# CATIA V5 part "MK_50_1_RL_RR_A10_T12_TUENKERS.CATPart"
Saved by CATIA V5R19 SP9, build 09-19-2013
Part number: MK_50_1_RL_RR_A10_T12_TUENKERS
Material "MISCHDICHTE": density 4776 kg/m3, Young's modulus 2e+11 Pa, Poisson ratio 0.266
Bounding box of the stored display mesh (mm): x -173.5 to 150.266, y -118.5 to 144, z -119.161 to 119.161
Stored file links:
  G:\Konstruktion\Modelle\Catia_V5\MK_50_1_RL_RR_A10_T12_TUENKERS.CATPart
  G:\Konstruktion\Modelle\Catia_V5\Spannarme\SPANNARM_KPL_50_A40_242838_TUENKERS.CATPart
  C:\Catia\Tuenkers_B19SP9HF86_64\win_b64\reffiles\standard\MetricThickPitch.txt
  G:\Konstruktion\Modelle\Catia_V5\Spannarme\SPANNARM_KPL_50_A10_216884_TUENKERS.CATPart
  G:\Konstruktion\Modelle\Catia_V5\MK2_50_1_A40_T00_TUENKERS.CATPart
  G:\Konstruktion\Modelle\Catia_V5\V2_50_1_BR3_ZL_ZR_RL_RR_A40_T12_TUENKERS.CATPart
  HANDHEBEL_KPL_50_63_TUENKERS.CATPart
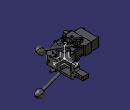
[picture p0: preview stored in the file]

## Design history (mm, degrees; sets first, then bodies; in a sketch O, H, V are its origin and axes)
AxisSystem1: origin (0, 0, 0), X (1, 0, 0), Y (0, 1, 0), Z (0, 0, 1)
Body1 (main body)
  Body2 "*DIT1\\*DIT8\\PartBody ( *SOL6 - wsp HANDHEBEL -  )"
    Solid1 "Solid.1": solid without history
  Assemble1: tool Body2
  Body3 "*DIT1\\*DIT9\\PartBody ( *SOL3 - wsp T 12 ABFRAGE -  )"
    Solid2 "Solid.1": solid without history
  Assemble2: tool Body3
  Body4 "*DIT1\\*DIT9\\Body.9 ( *SOL4 - wsp T 12 ABFRAGE -  )"
    Solid3 "Solid.1": solid without history
  Assemble3: tool Body4
  Body5 "*DIT1\\*DIT9\\Body.10 ( *SOL5 - wsp T 12 ABFRAGE -  )"
    Solid4 "Solid.1": solid without history
  Assemble4: tool Body5
  Body6 "*DIT1\\*DIT10\\*DIT17\\PartBody ( *SOL17 - wsp DREHBOLZEN -  )"
    Solid5 "Solid.1": solid without history
  Assemble5: tool Body6
  Body7 "*DIT1\\*DIT10\\*DIT18\\PartBody ( *SOL18 - wsp STOESSEL -  )"
    Solid6 "Solid.1": solid without history
  Assemble6: tool Body7
  Body8 "*DIT1\\*DIT10\\MK_MK2_50_1_A10_A11_A12_T12_081112_3D_xSET3_1.1\\PartBody ( *SOL13 - wsp GEHAEUSE -  )"
    Solid7 "Solid.1": solid without history
  Assemble7: tool Body8
  Body9 "*DIT1\\MK_MK2_50_1_A10_A11_A12_T12_081112_3D_xSET2.1\\PartBody ( *SOL1 - wsp MK_MK2 50_1 -  -Non Smart-  )"
    Solid8 "Solid.1": solid without history
  Assemble8: tool Body9
  Body10 "*DIT1\\MK_MK2_50_1_A10_A11_A12_T12_081112_3D_xSET2.1\\Body.2 ( *SOL2 - wsp MK_MK2 50_1 -  -Non Smart-  )"
    Solid9 "Solid.1": solid without history
  Assemble9: tool Body10
  Body11 "*DIT1\\MK_MK2_50_1_A10_A11_A12_T12_081112_3D_xSET2.1\\Body.3 ( *SOL24 - wsp MK_MK2 50_1 -  )"
    Solid10 "Solid.1": solid without history
  Assemble10: tool Body11
  Body12 "*DIT1\\MK_MK2_50_1_A10_A11_A12_T12_081112_3D_xSET2.1\\Body.4 ( *SOL25 - wsp MK_MK2 50_1 -  )"
    Solid11 "Solid.1": solid without history
  Assemble11: tool Body12
  Body13 "*DIT1\\MK_MK2_50_1_A10_A11_A12_T12_081112_3D_xSET2.1\\Body.5 ( *SOL26 - wsp MK_MK2 50_1 -  )"
    Solid12 "Solid.1": solid without history
  Assemble12: tool Body13
  Body14 "*DIT1\\MK_MK2_50_1_A10_A11_A12_T12_081112_3D_xSET2.1\\Body.6 ( *SOL27 - wsp MK_MK2 50_1 -  )"
    Solid13 "Solid.1": solid without history
  Assemble13: tool Body14
  Body15 "*DIT1\\MK_MK2_50_1_A10_A11_A12_T12_081112_3D_xSET2.1\\Body.7 ( *SOL28 - wsp MK_MK2 50_1 -  )"
    Solid14 "Solid.1": solid without history
  Assemble14: tool Body15
  Rotate1: Axis edge [XY plane of AxisSystem1 | ZX plane of AxisSystem1], Angle 90, ToTransfor Assemble14
Body16 "Spannarm_kpl_50_A10_216884_Tuenkers", material "Steel"
  Sketch1 on xy-plane, origin (0, 0, 0), H (1, 0, 0), V (0, 1, 0)
    line L1 (43, 144) -> (15, 144)
    line L2 (35.6421, 1.701) -> (16.9706, -16.9706)
    line L3 (9.5, 9.5) -> (9.5, -9.5)
    line L4 (9.5, 9.5) -> (-9.5, 9.5)
    line L5 (-16.9706, 16.9706) -> (-9.5, 9.5)
    line L6 (10.6421, 44.5833) -> (-16.9706, 16.9706)
    line L7 (16.5, 58.7254) -> (16.5, 78.5)
    line L8 (43, 144) -> (43, 80)
    line L9 (9.5, -9.5) -> (16.9706, -16.9706)
    point P8 (43, 9.0589)
    point P9 (16.5, 51.7188)
    reference intersected line E1 through (0, 0) direction (-1, 0)
    reference intersected line E2 through (0, 0) direction (0, 1)
    reference intersected line E3 through (0, 0) direction (-0.7071, -0.7071)
    line L10 (41.5, 78.5) -> (41.5, 15.8431)
    reference intersected line E4 through (0, 0) direction (0, 1) from yz-plane
    line L11 (15, 80) -> (15, 144)
    point P10 (15, 80)
    reference intersected line E5 through (0, 0) direction (0, 1) from yz-plane
    arc A1 centre (43, 78.5) radius 1.5 from (41.5, 78.5) to (43, 80) cw
    arc A2 centre (15, 78.5) radius 1.5 from (16.5, 78.5) to (15, 80) ccw
    arc A3 centre (21.5, 15.8431) radius 20 from (35.6421, 1.701) to (41.5, 15.8431) ccw
    arc A4 centre (-3.5, 58.7254) radius 20 from (10.6421, 44.5833) to (16.5, 58.7254) ccw
    length L3 = 19
    length L4 = 19
    angle L5 L4 = 45
    angle L3 L9 = 45
    distance L2 L6 = 48
    distance L4 L1 = 134.5
    distance P9 L4 = 42.2188
    distance L4 E1 = 9.5
    distance L3 E2 = 9.5
    distance L2 E3 = 24
    distance L10 E4 = 41.5
    distance E5 L11 = 15
    distance L7 L10 = 25
    distance L8 L11 = 28
    length L8 = 64
    radius A3 = 20
    radius A4 = 20
    radius A1 = 1.5
    radius A2 = 1.5
    length L11 = 64
    vertical: L3 V
    horizontal: L4 H
    tangency: A3 L10, L2 A3, L7 A2, L10 A1, L7 A4, L6 A4
  Pad1: profile Sketch1, direction (0, 0, 1), length 34, mirrored extent
  Chamfer1: length 0.1, angle 45, on edge [start face of Pad1 | face of Pad1 from Sketch1.L3]; edge [start face of Pad1 | face of Pad1 from Sketch1.L4]; edge [face of Pad1 from Sketch1.L4 | end face of Pad1]; edge [face of Pad1 from Sketch1.L3 | end face of Pad1]
  Sketch2 on face of Pad1 from Sketch1.L8, origin (43, 0, 0), H (0, 1, 0), V (0, 0, 1)
    line L1 (144, -10) -> (144, 10)
    line L2 (103, 10) -> (144, 10)
    arc A1 centre (103, 18) radius 8 from (103, 10) to (95, 18) cw
    line L3 (95, 18) -> (95, 21.0383)
    line L4 (-18, 34) -> (75, 34)
    line L5 (-18, 34) -> (-18, 25)
    line L6 (74, 25) -> (-18, 25)
    arc A2 centre (74, 19) radius 6 from (74, 25) to (80, 19) cw
    line L7 (80, 19) -> (80, -19)
    arc A3 centre (74, -19) radius 6 from (80, -19) to (74, -25) cw
    line L8 (-18, -25) -> (74, -25)
    line L9 (-18, -25) -> (-18, -34)
    line L10 (75, -34) -> (-18, -34)
    line L11 (95, -21.0383) -> (95, -18)
    arc A4 centre (103, -18) radius 8 from (95, -18) to (103, -10) cw
    line L12 (103, -10) -> (144, -10)
    reference intersected line E1 through (0, 0) direction (-1, 0) from xy-plane
    reference intersected line E2 through (0, 0) direction (0, 1) from zx-plane
    reference intersected line E3 through (0, 0) direction (0, 1) from zx-plane
    reference intersected line E4 through (0, 0) direction (0, 1) from zx-plane
    line L13 (-23, -39) -> (149, -39)
    line L14 (149, -39) -> (149, 39)
    line L15 (149, 39) -> (-23, 39)
    line L16 (-23, 39) -> (-23, -39)
    reference intersected line E5 through (0, 0) direction (-1, 0) from xy-plane
    reference intersected line E6 through (0, 0) direction (0, 1) from zx-plane
    line L17 (75.5176, -33.9319) -> (87.5882, -30.6976)
    point P18 (95, -24)
    arc A5 centre (85, -21.0383) radius 10 from (95, -21.0383) to (87.5882, -30.6976) cw
    arc A6 centre (75, -32) radius 2 from (75, -34) to (75.5176, -33.9319) ccw
    point P23 (75, -34)
    line L18 (87.5882, 30.6976) -> (75.5176, 33.9319)
    arc A7 centre (75, 32) radius 2 from (75, 34) to (75.5176, 33.9319) cw
    point P26 (75, 34)
    arc A8 centre (85, 21.0383) radius 10 from (87.5882, 30.6976) to (95, 21.0383) cw
    distance L12 E1 = 10
    distance L12 L2 = 20
    distance L4 L10 = 68
    distance L6 L8 = 50
    distance L10 L12 = 24
    distance L8 L10 = 9
    radius A2 = 6
    radius A3 = 6
    radius A1 = 8
    radius A4 = 8
    distance L7 E2 = 80
    distance L3 E3 = 95
    distance L1 L5 = 162
    distance E4 L1 = 144
    distance L16 L14 = 172
    distance L15 L13 = 78
    distance L13 E5 = 39
    distance L14 E6 = 149
    radius A5 = 10
    angle L10 L17 = 15
    radius A6 = 2
    distance L11 P23 = 20
    angle L4 L18 = 15
    distance P26 L3 = 20
    radius A8 = 10
    radius A7 = 2
    tangency: L6 A2, A2 L7, L7 A3, A3 L8, L3 A1, A1 L2, A4 L12, A4 L11, A5 L11, A5 L17, A6 L10, A6 L17, A7 L4, A7 L18, A8 L18, A8 L3
    vertical: L1 V, L14 V, L16 V
    horizontal: L12 H, L13 H, L15 H
    coincidence: L5 L9, L11 L3, L11 P18
  Pocket1: profile Sketch2, direction (-1, 0, 0), length 91
  Sketch3 on face of Pad1 from Sketch1.L8, origin (43, 131.0889, -0.3784), H (0, 1, 0), V (0, 0, 1)
    point P1 (3.9111, 0.3784)
    reference intersected line E1 through (0, 0.3784) direction (-1, 0) from xy-plane
    reference intersected line E2 through (-131.0889, 0) direction (0, 1) from zx-plane
    distance P1 E2 = 135
    coincidence: P1 E1
  Hole1: placed by Sketch3, at (43, 135, 0) direction (-1, 0, 0), diameter 6, through (limit type 6)
  Sketch4 on face of Pad1 from Sketch1.L8, origin (43, 113.9529, 0.5693), H (0, 1, 0), V (0, 0, 1)
    point P1 (-8.9529, -0.5693)
    reference projected point E1 (21.0471, -0.5693) from axis of face of Hole1
    reference intersected line E2 through (0, -0.5693) direction (-1, 0) from xy-plane
    distance P1 E1 = 30
    coincidence: P1 E2
  Hole2: placed by Sketch4, at (43, 105, 0) direction (-1, 0, 0), diameter 6, through (limit type 6)
  Sketch5 on face of Pad1 from Sketch1.L8, origin (43, 123.4122, -0.1089), H (0, 1, 0), V (0, 0, 1)
    point P1 (-3.4122, 0.1089)
    reference projected point E1 (11.5878, 0.1089) from axis of face of Hole1
    reference projected point E2 (-18.4122, 0.1089) from axis of face of Hole2
    distance P1 E1 = 15
    distance E2 P1 = 15
  Hole3: placed by Sketch5, at (43, 120, 0) direction (-1, 0, 0), diameter 9, through (limit type 6)
  Sketch6 on face of Pad1 from Sketch1.L8, origin (43, 93.5248, 1.4062), H (0, 1, 0), V (0, 0, 1)
    point P1 (-3.5248, -1.4062)
    reference projected point E1 (26.4752, -1.4062) from axis of face of Hole3
    reference projected point E2 (11.4752, -1.4062) from axis of face of Hole2
    distance P1 E1 = 30
    distance P1 E2 = 15
  Hole4: placed by Sketch6, at (43, 90, 0) direction (-1, 0, 0), diameter 9, through (limit type 6)
  Sketch7 on face of Pad1 from Sketch1.L9, origin (13.7879, -13.7879, 28.7565), H (0.7071, -0.7071, 0), V (0, 0, 1)
    point P1 (-1.4991, 0.2435)
    reference intersected line E1 through (0, -28.7565) direction (-1, 0) from xy-plane
    reference projected line E2 (-19.4991, -62.7565) -> (-19.4991, 5.2435) from edge [face of Pad1 from Sketch1.L3 | face of Pad1 from Sketch1.L4]
    distance P1 E1 = 29
    distance E2 P1 = 18
  Hole5: placed by Sketch7, at (12.7279, -12.7279, 29) direction (0.7071, 0.7071, 0), diameter 4.917, depth 16, V-bottom angle 120, threaded "M6", thread diameter 6, thread depth 14, pitch 1
  RectPattern1: of Hole5, direction 1 instances 2, spacing 58, along edge [face of Pad1 from Sketch1.L3 | face of Pad1 from Sketch1.L4] reversed, direction 2 instances 2, spacing 36, along edge [face of Pad1 from Sketch1.L9 | face of Pocket1] reversed
  Body17 "KLEMMFLANSCH KPL"
    Sketch8 on xy-plane, origin (0, 0, 0), H (1, 0, 0), V (0, 1, 0)
      line L1 (-18.3848, 15.5563) -> (-26.8771, 7.064)
      line L2 (-26.8771, 7.064) -> (-18.7454, -1.0677)
      line L3 (-18.7454, -1.0677) -> (-23.6951, -6.0175)
      line L4 (-23.6951, -6.0175) -> (-6.0175, -23.6951)
      line L5 (-6.0175, -23.6951) -> (-1.0677, -18.7454)
      line L6 (-1.0677, -18.7454) -> (7.064, -26.8771)
      line L7 (7.064, -26.8771) -> (16.9635, -16.9776)
      line L8 (16.9635, -16.9776) -> (9.3267, -9.3409)
      line L9 (9.3267, -9.3409) -> (-9.3409, -9.3409)
      point P10 (-9.3409, -9.3409)
      line L10 (-9.3409, -9.3409) -> (-9.3409, 6.5125)
      line L11 (-9.3409, 6.5125) -> (-18.3848, 15.5563)
      reference intersected line E1 through (0, 0) direction (-0.7071, -0.7071)
      reference intersected line E2 through (0, 0) direction (-0.7071, 0.7071)
      distance L4 L8 = 21
      angle L5 L6 = 90
      angle L9 L8 = 45
      distance L7 L5 = 11.5
      distance L5 L3 = 25
      distance L7 L1 = 48
      distance P10 L8 = 13.2
      distance P10 L5 = 12.5
      distance L4 L6 = 7
      angle L9 L10 = 90
      distance E2 L11 = 2
      distance L11 L8 = 1.99
      coincidence: L2 L6, E1 P10
    Pad2: profile Sketch8, direction (0, 0, 1), length 34, opposite side length -24
    Sketch9 on face of Pad2 from Sketch8.L6, origin (-9.9066, -9.9066, 0), H (0.7071, -0.7071, 0), V (0, 0, 1)
      circle A1 centre (18, 29) radius 5
      point P1 (18, 29)
      point P2 (18, 29)
      reference projected line E1 (12.5, 34) -> (24, 34) from edge [face of Pad2 from Sketch8.L6 | end face of Pad2]
      reference projected line E2 (24, 24) -> (24, 34) from edge [face of Pad2 from Sketch8.L7 | face of Pad2 from Sketch8.L6]
      radius A1 = 5
      distance E1 P2 = 5
      distance P2 E2 = 6
      coincidence: P2 P1
    Pad3: profile Sketch9, direction (-0.7071, -0.7071, 0), length 1.2
    RectPattern2: of Pad3, direction 1 instances 2, spacing 36, along edge [start face of Pad2 | face of Pad2 from Sketch8.L4] reversed
    Chamfer2: length 0.1, angle 45, on edge [face of Pad3 from Sketch9.A1 | end face of Pad3]; edge [face of RectPattern2 | face of RectPattern2]
    Sketch10 on face of Pad2 from Sketch8.L6, origin (-9.9066, -9.9066, 0), H (0.7071, -0.7071, 0), V (0, 0, 1)
      circle A1 centre (18, 29) radius 3
      point P1 (18, 29)
      reference projected line E1 (12.5, 24) -> (24, 24) from edge [start face of Pad2 | face of Pad2 from Sketch8.L6]
      reference projected line E2 (24, 24) -> (24, 34) from edge [face of Pad2 from Sketch8.L7 | face of Pad2 from Sketch8.L6]
      radius A1 = 3
      distance P1 E1 = 5
      distance E2 P1 = 6
    Pad4: profile Sketch10, direction (0.7071, 0.7071, 0), length 20
    RectPattern3: of Pad4, direction 1 instances 2, spacing 36, along edge [start face of Pad2 | face of Pad2 from Sketch8.L4] reversed
    Sketch11 on end face of Pad3, origin (-10.7551, -10.7551, 0), H (0.7071, -0.7071, 0), V (0, 0, 1)
      circle A1 centre (18, 29) radius 5
      point P1 (18, 29)
      circle A2 centre (-18, 29) radius 5
      point P2 (-18, 29)
      reference projected line E1 (-24, 24) -> (-12.5, 24) from edge [start face of Pad2 | face of Pad2 from Sketch8.L2]
      reference projected line E2 (12.5, 24) -> (24, 24) from edge [start face of Pad2 | face of Pad2 from Sketch8.L6]
      reference projected line E3 (24, 24) -> (24, 34) from edge [face of Pad2 from Sketch8.L7 | face of Pad2 from Sketch8.L6]
      reference projected line E4 (-24, 24) -> (-24, 34) from edge [face of Pad2 from Sketch8.L2 | face of Pad2 from Sketch8.L1]
      radius A1 = 5
      radius A2 = 5
      distance E1 P2 = 5
      distance E2 P1 = 5
      distance E3 P1 = 6
      distance E4 P2 = 6
    Pad5: profile Sketch11, direction (-0.7071, -0.7071, 0), length 6
    Fillet1: radius 0.5, on edge [face of Pad5 from Sketch11.A1 | end face of Pad5]; edge [face of Pad5 from Sketch11.A2 | end face of Pad5]
    Chamfer3: length 0.1, angle 45, on edge [face of Pad2 from Sketch8.L9 | end face of Pad2]; edge [face of Pad2 from Sketch8.L10 | end face of Pad2]
    Mirror1: of the body so far, about xy-plane
  Assemble15: tool Body17
  Sketch12 on face of Pocket1 from Sketch2.L6, origin (0, 0, 25), H (1, 0, 0), V (0, -1, 0)
    line L1 (16.9706, 16.9706) -> (9.5, 9.5)
    line L2 (9.5, 9.5) -> (9.5, -9.5)
    point P3 (9.5, -9.5)
    line L3 (9.5, -9.5) -> (-9.5, -9.5)
    line L4 (-9.5, -9.5) -> (-16.9706, -16.9706)
    line L5 (-16.9706, -16.9706) -> (0.7071, -34.6482)
    line L6 (0.7071, -34.6482) -> (34.6482, -0.7071)
    line L7 (34.6482, -0.7071) -> (16.9706, 16.9706)
    reference intersected line E1 through (0, 0) direction (0.7071, 0.7071)
    reference intersected line E2 through (0, 0) direction (0.7071, -0.7071)
    reference intersected line E3 through (0, 0) direction (0.7071, -0.7071)
    distance L1 L6 = 25
    angle L2 L3 = 90
    length L2 = 19
    length L3 = 19
    distance L7 L5 = 48
    distance L7 E3 = 24
    coincidence: E1 L1, L1 L4, E2 P3
  Pad6: profile Sketch12, direction (0, 0, -1), length 1
  Mirror2: of Pad6, Sketch12, about xy-plane
Body18 "ENDLAGENRASTE_LINKS"
  Body19 "LUMP108"
    Solid15 "Manifold Solid #2147": solid without history
  Assemble16: tool Body19
  Body20 "LUMP109"
    Solid16 "Manifold Solid #2556": solid without history
  Assemble17: tool Body20
  Body21 "LUMP110"
    Solid17 "Manifold Solid #2941": solid without history
  Assemble18: tool Body21
  Body22 "LUMP111"
    Solid18 "Manifold Solid #3571": solid without history
  Assemble19: tool Body22
  Body23 "LUMP112"
    Solid19 "Manifold Solid #4879": solid without history
  Assemble20: tool Body23
  Body24 "LUMP114"
    Solid20 "Manifold Solid #6444": solid without history
  Assemble21: tool Body24
  Body25 "LUMP117"
    Solid21 "Manifold Solid #8121": solid without history
  Assemble22: tool Body25
  Body26 "LUMP118"
    Solid22 "Manifold Solid #9264": solid without history
  Assemble23: tool Body26
  Body27 "LUMP120"
    Solid23 "Manifold Solid #10792": solid without history
  Assemble24: tool Body27
  Body28 "LUMP122"
    Solid24 "Manifold Solid #11586": solid without history
  Assemble25: tool Body28
  Body29 "LUMP126"
    Solid25 "Manifold Solid #12918": solid without history
  Assemble26: tool Body29
  Body30 "LUMP127"
    Solid26 "Manifold Solid #13327": solid without history
  Assemble27: tool Body30
  Body31 "LUMP130"
    Solid27 "Manifold Solid #14250": solid without history
  Assemble28: tool Body31
  Body32 "LUMP132"
    Solid28 "Manifold Solid #15068": solid without history
  Assemble29: tool Body32
  Body33 "LUMP133"
    Solid29 "Manifold Solid #15325": solid without history
  Assemble30: tool Body33
  Body34 "LUMP134"
    Solid30 "Manifold Solid #15582": solid without history
  Assemble31: tool Body34
  Body35 "LUMP135"
    Solid31 "Manifold Solid #15839": solid without history
  Assemble32: tool Body35
  Body36 "LUMP124"
    Solid32 "Manifold Solid #12404": solid without history
  Assemble33: tool Body36
  Rotate2: Axis edge, Angle 90, ToTransfor Assemble33
Body37 "ENDLAGENRASTE_RECHTS"
  Solid33 "Manifold Solid #290": solid without history
  Body38 "LUMP105"
    Solid34 "Manifold Solid #920": solid without history
  Assemble34: tool Body38
  Body39 "LUMP106"
    Solid35 "Manifold Solid #1329": solid without history
  Assemble35: tool Body39
  Body40 "LUMP107"
    Solid36 "Manifold Solid #1738": solid without history
  Assemble36: tool Body40
  Body41 "LUMP113"
    Solid37 "Manifold Solid #6187": solid without history
  Assemble37: tool Body41
  Body42 "LUMP115"
    Solid38 "Manifold Solid #6701": solid without history
  Assemble38: tool Body42
  Body43 "LUMP116"
    Solid39 "Manifold Solid #7411": solid without history
  Assemble39: tool Body43
  Body44 "LUMP119"
    Solid40 "Manifold Solid #10407": solid without history
  Assemble40: tool Body44
  Body45 "LUMP121"
    Solid41 "Manifold Solid #11177": solid without history
  Assemble41: tool Body45
  Body46 "LUMP123"
    Solid42 "Manifold Solid #11995": solid without history
  Assemble42: tool Body46
  Body47 "LUMP124"
    Solid43 "Manifold Solid #12404": solid without history
    Symmetry1: Reference ZX plane of AxisSystem1, ToTransfor Solid43
  Assemble43: tool Body47
  Body48 "LUMP125"
    Solid44 "Manifold Solid #12661": solid without history
  Assemble44: tool Body48
  Body49 "LUMP128"
    Solid45 "Manifold Solid #13736": solid without history
  Assemble45: tool Body49
  Body50 "LUMP129"
    Solid46 "Manifold Solid #13993": solid without history
  Assemble46: tool Body50
  Body51 "LUMP131"
    Solid47 "Manifold Solid #14659": solid without history
  Assemble47: tool Body51
  Body52 "LUMP136"
    Solid48 "Manifold Solid #16096": solid without history
  Assemble48: tool Body52
  Rotate3: Axis edge, Angle 90, ToTransfor Assemble48
Body53 "Handhebel_KPL_218625_TUENKERS.1"
  Solid49: solid without history
  Body54 "Handhebel_KPL_218625_TUENKERS.2"
    Solid50: solid without history
  Assemble49: tool Body54
  Translate1: Direction edge [ZX plane of AxisSystem1 | YZ plane of AxisSystem1], ToTransfor Assemble49, Length 25
  Translate2: Direction edge [XY plane of AxisSystem1 | ZX plane of AxisSystem1], ToTransfor Translate1, Length -68
  Translate3: Direction edge [YZ plane of AxisSystem1 | XY plane of AxisSystem1], ToTransfor Translate2, Length -4
Body55 "Handhebel_KPL_218625_TUENKERS.1"
  Solid51: solid without history
  Body56 "Handhebel_KPL_218625_TUENKERS.2"
    Solid52: solid without history
  Assemble50: tool Body56
  Translate4: Direction edge [ZX plane of AxisSystem1 | YZ plane of AxisSystem1], Length 25, ToTransfor Assemble50
  Translate5: Direction edge [XY plane of AxisSystem1 | ZX plane of AxisSystem1], Length -68, ToTransfor Translate4
  Translate6: Direction edge [YZ plane of AxisSystem1 | XY plane of AxisSystem1], Length -4, ToTransfor Translate5
  Symmetry2: ToTransfor Translate6, Reference XY plane of AxisSystem1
